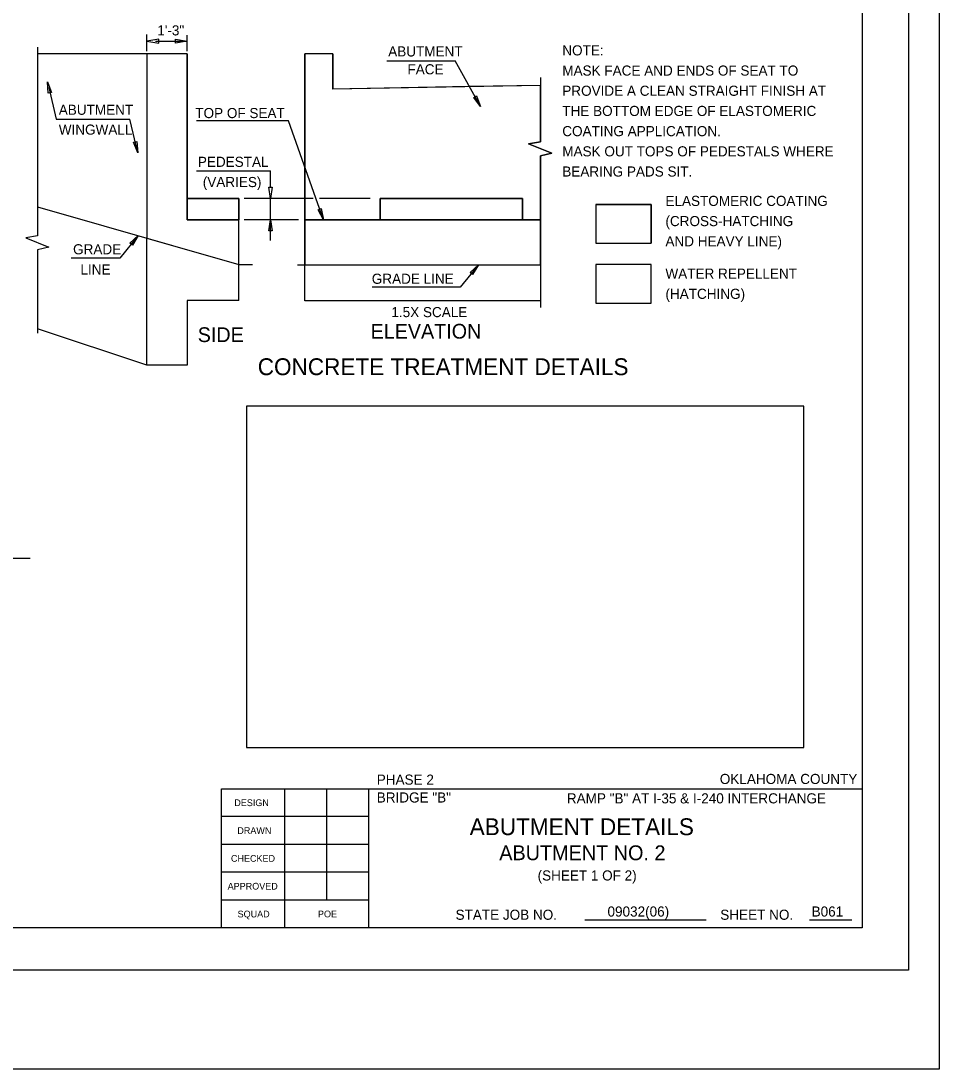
# Model space of a CAD drawing. Extents: x 2146724 to 2153191, y 139029 to 143935.
# Drawn here: x 2147024.69 to 2147068.25, y 143268.36 to 143318.11 of the extents above; entities that cross this region are included whole.
import ezdxf

# ---------------------------------------------------------------- set-up
doc = ezdxf.new("R2010")
doc.units = 0
for name, color, linetype in [('4', 7, 'Continuous'), ('PR_Bridge_Abutment', 7, 'Continuous'), ('PR_Dimensions', 7, 'Continuous'), ('SHT_Plot_Shape_Full', 7, 'Continuous'), ('SHT_Plot_Shape_Half', 7, 'Continuous'), ('SHT_Sheet_Border', 7, 'Continuous'), ('SHT_Standard_Sheet_Lines', 7, 'Continuous'), ('SHT_Standard_Sheet_Txt', 7, 'Continuous'), ('T', 7, 'Continuous'), ('T-Subtitle', 7, 'Continuous'), ('T-Title', 7, 'Continuous')]:
    doc.layers.add(name, color=color, linetype=linetype)

msp = doc.modelspace()

# ---------------------------------------------------------------- linework, layer by layer
at = {"layer": '4'}
msp.add_lwpolyline([(2147051.971, 143306.543), (2147051.971, 143304.711), (2147054.597, 143304.711), (2147054.597, 143306.543)], close=True, dxfattribs=at)
at = {"layer": 'PR_Bridge_Abutment'}
for p, q in [((2147032.581, 143316.543), (2147025.473, 143316.543)), ((2147030.664, 143316.543), (2147030.664, 143307.797)), ((2147032.581, 143316.543), (2147032.581, 143308.665)), ((2147038.156, 143306.532), (2147038.156, 143316.551)), ((2147039.485, 143316.551), (2147038.156, 143316.551)), ((2147039.485, 143316.551), (2147039.485, 143314.868)), ((2147049.339, 143315.05), (2147039.485, 143314.868)), ((2147032.581, 143309.673), (2147035.035, 143309.673)), ((2147035.035, 143309.673), (2147035.035, 143308.669)), ((2147035.035, 143308.665), (2147032.581, 143308.665)), ((2147035.035, 143306.539), (2147035.035, 143308.665)), ((2147030.664, 143301.762), (2147030.664, 143307.797)), ((2147035.035, 143304.83), (2147035.035, 143306.539)), ((2147038.156, 143304.824), (2147038.156, 143306.532)), ((2147032.581, 143304.83), (2147032.581, 143301.762)), ((2147035.035, 143304.83), (2147032.581, 143304.83)), ((2147049.339, 143304.824), (2147038.156, 143304.824)), ((2147030.664, 143301.762), (2147025.473, 143303.492)), ((2147032.581, 143301.762), (2147030.664, 143301.762))]:
    msp.add_line(p, q, dxfattribs=at)
msp.add_lwpolyline([(2147032.581, 143308.665), (2147035.035, 143308.665), (2147035.035, 143309.673), (2147032.581, 143309.673)], close=True, dxfattribs=at)
msp.add_lwpolyline([(2147038.156, 143308.673), (2147041.74, 143308.673), (2147041.74, 143309.673), (2147048.49, 143309.673), (2147048.49, 143308.673), (2147049.339, 143308.673)], dxfattribs=at)
at = {"layer": 'PR_Dimensions'}
for p, q in [((2147030.664, 143316.676), (2147030.664, 143317.463)), ((2147031.075, 143317.141), (2147032.581, 143317.141)), ((2147032.581, 143316.676), (2147032.581, 143317.436)), ((2147025.473, 143316.859), (2147025.473, 143307.903)), ((2147032.581, 143316.543), (2147030.664, 143316.543)), ((2147030.664, 143316.543), (2147030.664, 143307.797)), ((2147039.485, 143316.551), (2147038.156, 143316.551)), ((2147039.485, 143314.868), (2147039.485, 143316.551)), ((2147042.055, 143316.209), (2147045.288, 143316.209)), ((2147046.5, 143314.051), (2147045.288, 143316.209)), ((2147049.339, 143315.414), (2147049.339, 143312.366)), ((2147049.339, 143312.366), (2147049.339, 143315.05)), ((2147026.004, 143314.955), (2147026.359, 143313.438)), ((2147026.359, 143313.438), (2147029.858, 143313.438)), ((2147030.234, 143311.851), (2147029.858, 143313.438)), ((2147037.389, 143313.366), (2147033.025, 143313.366)), ((2147039.04, 143308.673), (2147037.389, 143313.366)), ((2147049.339, 143312.366), (2147048.78, 143312.275)), ((2147048.78, 143312.275), (2147049.339, 143312.366)), ((2147048.78, 143312.275), (2147049.878, 143311.825)), ((2147049.878, 143311.825), (2147048.78, 143312.275)), ((2147049.878, 143311.825), (2147049.339, 143311.707)), ((2147049.339, 143311.707), (2147049.878, 143311.825)), ((2147049.339, 143311.707), (2147049.339, 143304.504)), ((2147049.339, 143308.673), (2147049.339, 143311.707)), ((2147033.016, 143310.997), (2147036.53, 143310.997)), ((2147036.53, 143310.209), (2147036.53, 143310.997)), ((2147032.581, 143309.673), (2147032.581, 143308.665)), ((2147038.552, 143309.681), (2147035.278, 143309.681)), ((2147036.53, 143307.684), (2147036.53, 143309.681)), ((2147041.266, 143309.681), (2147038.862, 143309.681)), ((2147025.473, 143309.29), (2147035.035, 143306.539)), ((2147054.597, 143309.398), (2147051.971, 143309.398)), ((2147051.971, 143309.398), (2147051.971, 143307.566)), ((2147054.597, 143307.566), (2147054.597, 143309.398)), ((2147035.035, 143308.665), (2147032.581, 143308.665)), ((2147035.035, 143306.539), (2147035.035, 143308.665)), ((2147037.851, 143308.673), (2147035.278, 143308.673)), ((2147038.156, 143308.673), (2147039.04, 143308.673)), ((2147039.04, 143308.673), (2147038.156, 143308.673)), ((2147038.156, 143308.673), (2147038.156, 143306.532)), ((2147041.74, 143308.673), (2147039.04, 143308.673)), ((2147041.74, 143308.673), (2147048.49, 143308.673)), ((2147041.74, 143308.673), (2147048.49, 143308.673)), ((2147048.49, 143308.673), (2147041.74, 143308.673)), ((2147049.339, 143308.673), (2147048.49, 143308.673)), ((2147049.339, 143306.532), (2147049.339, 143308.673)), ((2147025.473, 143307.903), (2147024.914, 143307.812)), ((2147024.914, 143307.812), (2147026.012, 143307.362)), ((2147030.664, 143307.797), (2147035.035, 143306.539)), ((2147051.971, 143307.566), (2147054.597, 143307.566)), ((2147026.012, 143307.362), (2147025.473, 143307.244)), ((2147025.473, 143307.244), (2147025.473, 143303.281)), ((2147035.035, 143306.539), (2147035.678, 143306.539)), ((2147037.804, 143306.532), (2147049.339, 143306.532)), ((2147012.218, 143292.613), (2147025.123, 143292.613))]:
    msp.add_line(p, q, dxfattribs=at)
for points in [[(2147031.224, 143317.235), (2147030.664, 143317.141), (2147031.224, 143317.048)], [(2147032.021, 143317.235), (2147032.581, 143317.141), (2147032.021, 143317.048)], [(2147025.987, 143314.68), (2147025.944, 143315.211), (2147026.141, 143314.716)], [(2147046.311, 143314.549), (2147046.5, 143314.051), (2147046.173, 143314.472)], [(2147030.189, 143312.382), (2147030.234, 143311.851), (2147030.035, 143312.346)], [(2147036.609, 143310.209), (2147036.53, 143309.681), (2147036.451, 143310.209)], [(2147038.94, 143309.197), (2147039.04, 143308.673), (2147038.791, 143309.144)], [(2147036.451, 143308.146), (2147036.53, 143308.673), (2147036.609, 143308.146)], [(2147029.853, 143307.557), (2147030.246, 143307.917), (2147029.975, 143307.458)], [(2147045.999, 143306.173), (2147046.392, 143306.532), (2147046.122, 143306.073)], [(2147035.384, 143283.624), (2147061.843, 143283.624), (2147061.843, 143299.823), (2147035.384, 143299.823)]]:
    msp.add_lwpolyline(points, close=True, dxfattribs=at)
for points in [[(2147032.581, 143308.665), (2147032.581, 143309.673), (2147032.581, 143316.543)], [(2147038.156, 143316.551), (2147038.156, 143309.681), (2147038.156, 143308.673)], [(2147049.339, 143315.05), (2147045.974, 143314.988), (2147039.485, 143314.868)], [(2147046.311, 143314.549), (2147046.5, 143314.051), (2147046.173, 143314.472), (2147046.242, 143314.51), (2147046.311, 143314.549)], [(2147032.581, 143308.665), (2147035.035, 143308.665), (2147035.035, 143309.673), (2147032.581, 143309.673)], [(2147039.04, 143308.673), (2147041.74, 143308.673), (2147041.74, 143309.673), (2147048.49, 143309.673), (2147048.49, 143308.673), (2147049.339, 143308.673)], [(2147048.49, 143308.673), (2147048.49, 143309.673), (2147041.74, 143309.673), (2147041.74, 143308.673)], [(2147039.04, 143308.673), (2147038.791, 143309.144), (2147038.94, 143309.197), (2147039.04, 143308.673)], [(2147030.246, 143307.917), (2147029.378, 143306.846), (2147027.065, 143306.846)], [(2147038.156, 143306.532), (2147046.392, 143306.532), (2147049.339, 143306.532)], [(2147046.392, 143306.532), (2147045.524, 143305.462), (2147041.355, 143305.462)], [(2147051.971, 143306.543), (2147051.971, 143304.711), (2147054.597, 143304.711), (2147054.597, 143306.543), (2147051.971, 143306.543)]]:
    msp.add_lwpolyline(points, dxfattribs=at)
at = {"layer": 'SHT_Plot_Shape_Full'}
msp.add_lwpolyline([(2146924.253, 143364.357), (2147068.253, 143364.357), (2147068.253, 143268.357), (2146924.253, 143268.357)], close=True, dxfattribs=at)
at = {"layer": 'SHT_Plot_Shape_Half'}
msp.add_lwpolyline([(2146930.803, 143361.057), (2147066.803, 143361.057), (2147066.803, 143273.057), (2146930.803, 143273.057)], close=True, dxfattribs=at)
at = {"layer": 'SHT_Sheet_Border'}
for p, q in [((2147034.203, 143275.057), (2147034.203, 143281.657)), ((2147034.203, 143281.657), (2147064.603, 143281.657)), ((2147041.203, 143275.057), (2147041.203, 143281.66)), ((2147041.203, 143275.057), (2147041.203, 143281.66))]:
    msp.add_line(p, q, dxfattribs=at)
msp.add_lwpolyline([(2147064.603, 143275.057), (2146938.603, 143275.057), (2146938.603, 143359.057), (2147064.603, 143359.057)], close=True, dxfattribs=at)
at = {"layer": 'SHT_Standard_Sheet_Lines'}
for p, q in [((2147037.203, 143275.057), (2147037.203, 143281.66)), ((2147039.203, 143276.377), (2147039.203, 143281.66)), ((2147051.446, 143275.441), (2147057.207, 143275.441)), ((2147051.446, 143275.441), (2147057.207, 143275.441)), ((2147062.105, 143275.441), (2147064.115, 143275.441)), ((2147062.105, 143275.441), (2147064.115, 143275.441))]:
    msp.add_line(p, q, dxfattribs=at)
for points in [[(2147041.203, 143280.337), (2147034.203, 143280.337)], [(2147041.203, 143279.017), (2147034.203, 143279.017)], [(2147041.203, 143277.697), (2147034.203, 143277.697)], [(2147041.203, 143276.377), (2147034.203, 143276.377)]]:
    msp.add_lwpolyline(points, dxfattribs=at)
at = {"layer": 'T'}
for p, q in [((2147051.971, 143309.398), (2147051.971, 143307.566)), ((2147051.971, 143309.398), (2147054.597, 143309.398)), ((2147054.597, 143309.398), (2147054.597, 143307.566)), ((2147051.971, 143307.566), (2147054.597, 143307.566))]:
    msp.add_line(p, q, dxfattribs=at)
msp.add_lwpolyline([(2147051.971, 143309.398), (2147051.971, 143307.566), (2147054.597, 143307.566), (2147054.597, 143309.398)], close=True, dxfattribs=at)

# ---------------------------------------------------------------- texts
at = {"layer": 'Defpoints'}
msp.add_text('1.5X SCALE', height=0.48, dxfattribs=at).set_placement((2147042.266, 143304.046))
at = {"layer": 'SHT_Standard_Sheet_Txt'}
for s, height, p in [('DESIGN', 0.32, (2147034.812, 143280.837)), ('DRAWN', 0.32, (2147034.955, 143279.516)), ('CHECKED', 0.32, (2147034.654, 143278.195)), ('APPROVED', 0.32, (2147034.497, 143276.875)), ('SQUAD', 0.32, (2147034.969, 143275.554)), ('POE', 0.32, (2147038.783, 143275.557)), ('STATE JOB NO.', 0.48, (2147045.311, 143275.441)), ('STATE JOB NO.', 0.48, (2147045.311, 143275.441)), ('SHEET NO. ', 0.48, (2147057.872, 143275.441)), ('SHEET NO. ', 0.48, (2147057.872, 143275.441))]:
    msp.add_text(s, height=height, dxfattribs=at).set_placement(p)
at = {"layer": 'T'}
for s, height, p in [('1\'-3"', 0.48, (2147031.157, 143317.419)), ('ABUTMENT', 0.48, (2147042.116, 143316.42)), ('NOTE:', 0.48, (2147050.376, 143316.47)), ('FACE', 0.48, (2147043.029, 143315.571)), ('MASK FACE AND ENDS OF SEAT TO ', 0.48, (2147050.376, 143315.511)), ('PROVIDE A CLEAN STRAIGHT FINISH AT ', 0.48, (2147050.376, 143314.553)), ('ABUTMENT', 0.48, (2147026.483, 143313.65)), ('THE BOTTOM EDGE OF ELASTOMERIC ', 0.48, (2147050.376, 143313.595)), ('TOP OF SEAT', 0.48, (2147032.962, 143313.494)), ('WINGWALL', 0.48, (2147026.483, 143312.708)), ('COATING APPLICATION. ', 0.48, (2147050.376, 143312.636)), ('MASK OUT TOPS OF PEDESTALS WHERE ', 0.48, (2147050.376, 143311.678)), ('PEDESTAL', 0.48, (2147033.084, 143311.18)), ('BEARING PADS SIT.', 0.48, (2147050.376, 143310.72)), ('(VARIES)', 0.48, (2147033.317, 143310.22)), ('ELASTOMERIC COATING', 0.48, (2147055.271, 143309.324)), ('(CROSS-HATCHING ', 0.48, (2147055.271, 143308.366)), ('AND HEAVY LINE)', 0.48, (2147055.271, 143307.408)), ('GRADE ', 0.48, (2147027.162, 143307.028)), ('LINE', 0.48, (2147027.511, 143306.068)), ('GRADE LINE', 0.48, (2147041.337, 143305.629)), ('WATER REPELLENT', 0.48, (2147055.271, 143305.872)), ('(HATCHING)', 0.48, (2147055.271, 143304.914)), ('PHASE 2', 0.48, (2147041.571, 143281.854)), ('OKLAHOMA COUNTY', 0.48, (2147057.85, 143281.886)), ('BRIDGE "B"', 0.48, (2147041.571, 143281.007)), ('RAMP "B" AT I-35 & I-240 INTERCHANGE', 0.48, (2147050.592, 143280.966)), ('(SHEET 1 OF 2)', 0.47917, (2147049.205, 143277.306)), ('09032(06)', 0.48, (2147052.521, 143275.594)), ('B061', 0.48, (2147062.207, 143275.594))]:
    msp.add_text(s, height=height, dxfattribs=at).set_placement(p)
at = {"layer": 'T-Subtitle'}
for s, height, p in [('SIDE', 0.7, (2147033.077, 143302.864)), ('ELEVATION', 0.7, (2147041.279, 143303.027)), ('ABUTMENT NO. 2', 0.70312, (2147047.385, 143278.27))]:
    msp.add_text(s, height=height, dxfattribs=at).set_placement(p)
at = {"layer": 'T-Title'}
for s, height, p in [('CONCRETE TREATMENT DETAILS', 0.8, (2147035.924, 143301.293)), ('ABUTMENT DETAILS', 0.79999, (2147045.982, 143279.458))]:
    msp.add_text(s, height=height, dxfattribs=at).set_placement(p)

doc.saveas('drawing.dxf')
